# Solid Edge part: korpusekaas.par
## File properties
Author: Türk
Template: iso part.par
Last saved by: Türk
Revision: 3
Application: Solid Edge
Accuracy: 0,990
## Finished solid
Body 1: solid body, 35 faces, 84 edges, 54 vertices.
  Faces by surface: plane 25, cylinder 8, cone 2
  Edges by curve: line 66, circle 18
Bounding box of the edges (mm): 140.000 x 10.000 x 100.000, from (-70, 0, -50) to (70, 10, 50).
Cylindrical faces by radius (mm): R15 x2, R16 x2, R19 x2, R20 x2
Conical faces (half-angle, radius in mm at the cone's reference point): 45 deg R20 x2
Planar faces by outward normal: +x 4, +y 1, +z 4, -x 4, -y 4, -z 4, oblique 4
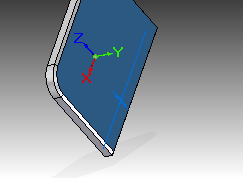
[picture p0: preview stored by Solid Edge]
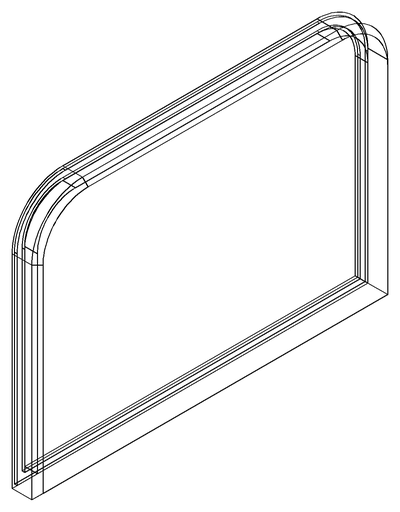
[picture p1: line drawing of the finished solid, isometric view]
